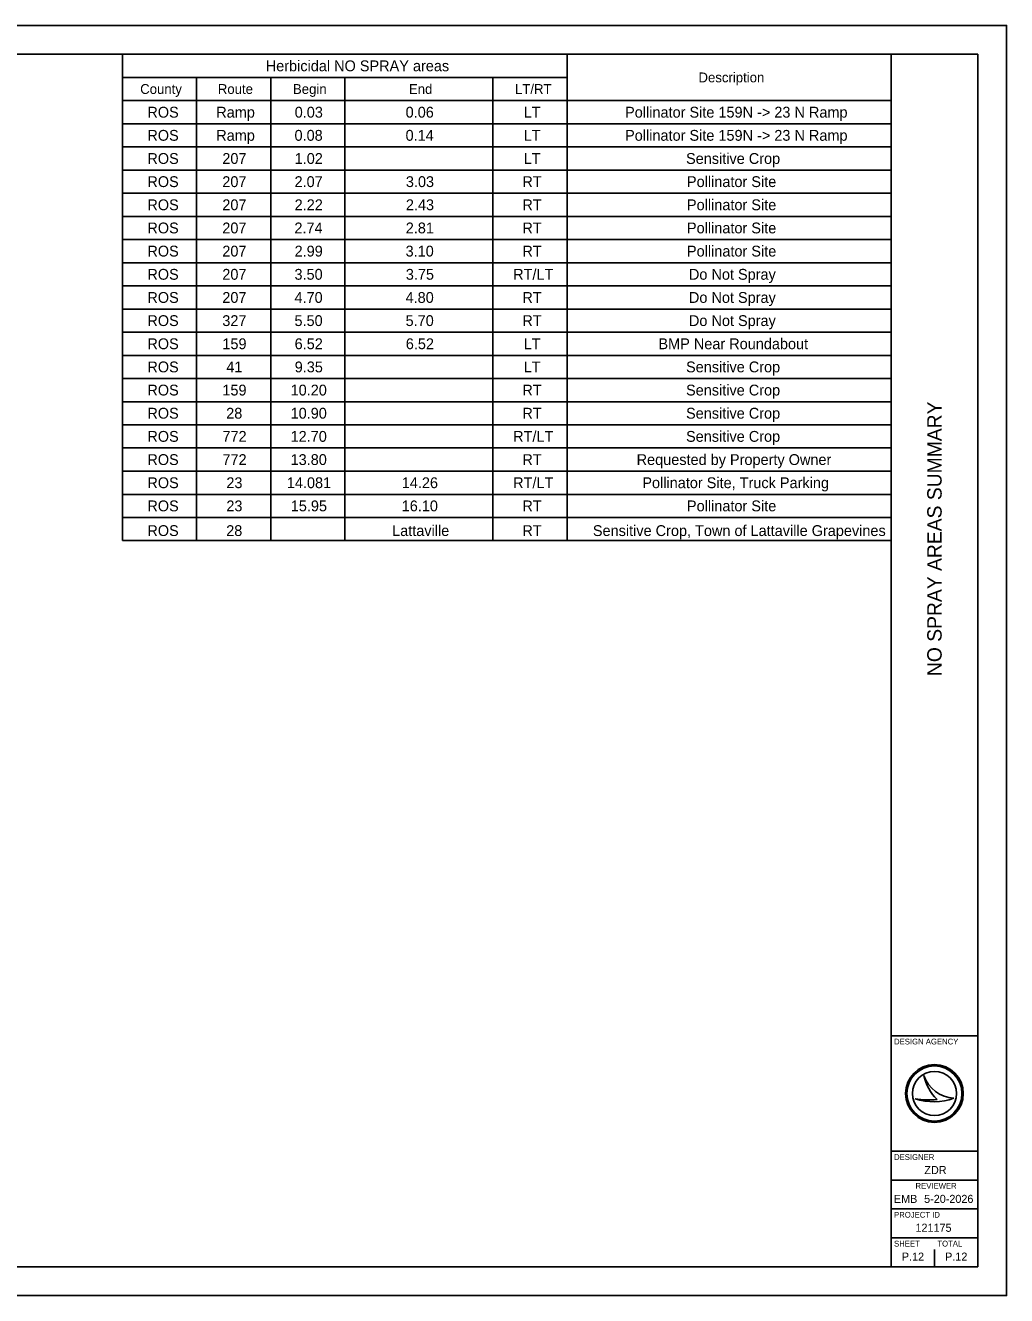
# Model space of a CAD drawing. Extents: x 0 to 34, y 0 to 22.
# Drawn here: x 17 to 34, y 0 to 22 of the extents above; entities that cross this region are included whole.
import ezdxf

# ---------------------------------------------------------------- set-up
doc = ezdxf.new("R2010")
doc.units = 0
for name, color, linetype in [('SH_Border', 7, 'Continuous'), ('SH_Cut_Line', 7, 'Continuous'), ('SH_Data', 7, 'Continuous'), ('SH_Text', 7, 'Continuous')]:
    doc.layers.add(name, color=color, linetype=linetype)

msp = doc.modelspace()

# ---------------------------------------------------------------- linework, layer by layer
at = {"layer": 'SH_Border'}
for p, q in [((32, 0.5), (32, 21.5)), ((32, 4.5), (33.5, 4.5)), ((32, 2.5), (33.5, 2.5)), ((32, 2), (33.5, 2)), ((32, 1.5), (33.5, 1.5)), ((32, 1), (33.5, 1))]:
    msp.add_line(p, q, dxfattribs=at)
msp.add_lwpolyline([(1.5, 21.5), (33.5, 21.5), (33.5, 0.5), (1.5, 0.5)], close=True, dxfattribs=at)
at = {"layer": 'SH_Cut_Line'}
msp.add_lwpolyline([(0, 0), (34, 0), (34, 22), (0, 22)], close=True, dxfattribs=at)
at = {"layer": 'SH_Data'}
for p, q in [((32.567, 3.81), (32.567, 3.81)), ((32.417, 3.41), (32.417, 3.41)), ((32.75, 3.5), (32.75, 3.5)), ((33.087, 3.419), (33.087, 3.419)), ((32.375, 0.675), (32.375, 0.675)), ((32.75, 0.5), (32.75, 0.8))]:
    msp.add_line(p, q, dxfattribs=at)
for radius in [0.5, 0.477, 0.477, 0.382]:
    msp.add_circle((32.75, 3.5), radius, dxfattribs=at)
for centre, radius, start, end in [((33.116, 3.998), 0.58, 198.9257, 198.9319), ((33.347, 3.97), 0.796, 191.6379, 191.6421), ((33.116, 3.998), 0.58, 198.9319, 267.1657), ((33.347, 3.97), 0.796, 191.6421, 226.0947), ((32.739, 4.37), 1.013, 251.4576, 290.0832), ((32.648, 4.654), 1.266, 259.4964, 259.4995), ((32.739, 4.37), 1.013, 251.4527, 251.4576), ((32.648, 4.654), 1.266, 259.4995, 276.6672)]:
    msp.add_arc(centre, radius, start, end, dxfattribs=at)
at = {"layer": 'SH_Text'}
for p, q in [((18.682, 21.5), (32, 21.5)), ((18.682, 21.5), (18.682, 13.076)), ((26.384, 21.5), (26.384, 13.076)), ((32, 21.5), (32, 13.076)), ((18.682, 21.099), (26.384, 21.099)), ((19.966, 21.099), (19.966, 13.076)), ((21.25, 21.099), (21.25, 13.076)), ((22.533, 21.099), (22.533, 13.076)), ((25.1, 21.099), (25.1, 13.076)), ((18.682, 20.698), (32, 20.698)), ((18.682, 20.297), (32, 20.297)), ((18.682, 19.895), (32, 19.895)), ((18.682, 19.494), (32, 19.494)), ((18.682, 19.093), (32, 19.093)), ((18.682, 18.692), (32, 18.692)), ((18.682, 18.291), (32, 18.291)), ((18.682, 17.89), (32, 17.89)), ((18.682, 17.489), (32, 17.489)), ((18.682, 17.088), (32, 17.088)), ((18.682, 16.686), (32, 16.686)), ((18.682, 16.285), (32, 16.285)), ((18.682, 15.884), (32, 15.884)), ((18.682, 15.483), (32, 15.483)), ((18.682, 15.082), (32, 15.082)), ((18.682, 14.681), (32, 14.681)), ((18.682, 14.28), (32, 14.28)), ((18.682, 13.878), (32, 13.878)), ((18.682, 13.477), (32, 13.477)), ((18.682, 13.076), (32, 13.076))]:
    msp.add_line(p, q, dxfattribs=at)

# ---------------------------------------------------------------- texts
at = {"layer": 'SH_Data'}
msp.add_text('NO SPRAY AREAS SUMMARY', height=0.25, rotation=90, dxfattribs=at).set_placement((32.875, 10.73))
for s, height, p in [('DESIGN AGENCY', 0.1, (32.05, 4.35)), ('DESIGNER', 0.1, (32.05, 2.35)), ('ZDR', 0.14, (32.575, 2.105)), ('REVIEWER', 0.1, (32.422, 1.85)), ('EMB', 0.14, (32.047, 1.605)), ('5-20-2026', 0.14, (32.571, 1.605)), ('PROJECT ID', 0.1, (32.05, 1.35)), ('121175', 0.14, (32.421, 1.105)), ('SHEET', 0.1, (32.05, 0.85)), ('TOTAL', 0.1, (32.8, 0.85)), ('P.12', 0.14, (32.185, 0.605)), ('P.12', 0.14, (32.935, 0.605))]:
    msp.add_text(s, height=height, dxfattribs=at).set_placement(p)
at = {"layer": 'SH_Text'}
for s, height, p in [('Herbicidal NO SPRAY areas', 0.18753, (21.164, 21.206)), ('Description', 0.17048, (28.662, 21.014)), ('County', 0.1705, (18.989, 20.813)), ('Route', 0.1705, (20.334, 20.813)), ('Begin', 0.1705, (21.636, 20.813)), ('End', 0.1705, (23.645, 20.813)), ('LT/RT', 0.1705, (25.483, 20.813)), ('ROS', 0.1875, (19.113, 20.403)), ('Ramp', 0.1875, (20.307, 20.403)), ('0.03', 0.1875, (21.666, 20.403)), ('0.06', 0.1875, (23.588, 20.403)), ('LT', 0.1875, (25.633, 20.403)), ('Pollinator Site 159N -> 23 N Ramp', 0.18753, (27.39, 20.403)), ('ROS', 0.1875, (19.113, 20.002)), ('Ramp', 0.1875, (20.307, 20.002)), ('0.08', 0.1875, (21.663, 20.002)), ('0.14', 0.1875, (23.587, 20.002)), ('LT', 0.1875, (25.633, 20.002)), ('Pollinator Site 159N -> 23 N Ramp', 0.18753, (27.39, 20.002)), ('ROS', 0.1875, (19.113, 19.601)), ('207', 0.1875, (20.412, 19.601)), ('1.02', 0.1875, (21.665, 19.601)), ('LT', 0.1875, (25.633, 19.601)), ('Sensitive Crop', 0.18753, (28.446, 19.601)), ('ROS', 0.1875, (19.113, 19.2)), ('207', 0.1875, (20.412, 19.2)), ('2.07', 0.1875, (21.663, 19.2)), ('3.03', 0.1875, (23.592, 19.2)), ('RT', 0.1875, (25.61, 19.2)), ('Pollinator Site', 0.18753, (28.462, 19.2)), ('ROS', 0.1875, (19.113, 18.799)), ('207', 0.1875, (20.412, 18.799)), ('2.22', 0.1875, (21.665, 18.799)), ('2.43', 0.1875, (23.592, 18.799)), ('RT', 0.1875, (25.61, 18.799)), ('Pollinator Site', 0.18753, (28.462, 18.799)), ('ROS', 0.1875, (19.113, 18.398)), ('207', 0.1875, (20.412, 18.398)), ('2.74', 0.1875, (21.661, 18.398)), ('2.81', 0.1875, (23.59, 18.398)), ('RT', 0.1875, (25.61, 18.398)), ('Pollinator Site', 0.18753, (28.462, 18.398)), ('ROS', 0.1875, (19.113, 17.997)), ('207', 0.1875, (20.412, 17.997)), ('2.99', 0.1875, (21.664, 17.997)), ('3.10', 0.1875, (23.587, 17.997)), ('RT', 0.1875, (25.61, 17.997)), ('Pollinator Site', 0.18753, (28.462, 17.997)), ('ROS', 0.1875, (19.113, 17.595)), ('207', 0.1875, (20.412, 17.595)), ('3.50', 0.1875, (21.662, 17.595)), ('3.75', 0.1875, (23.591, 17.595)), ('RT/LT', 0.1875, (25.451, 17.595)), ('Do Not Spray', 0.18753, (28.496, 17.595)), ('ROS', 0.1875, (19.113, 17.194)), ('207', 0.1875, (20.412, 17.194)), ('4.70', 0.1875, (21.662, 17.194)), ('4.80', 0.1875, (23.587, 17.194)), ('RT', 0.1875, (25.61, 17.194)), ('Do Not Spray', 0.18753, (28.496, 17.194)), ('ROS', 0.1875, (19.113, 16.793)), ('327', 0.1875, (20.412, 16.793)), ('5.50', 0.1875, (21.662, 16.793)), ('5.70', 0.1875, (23.587, 16.793)), ('RT', 0.1875, (25.61, 16.793)), ('Do Not Spray', 0.18753, (28.496, 16.793)), ('ROS', 0.1875, (19.113, 16.392)), ('159', 0.1875, (20.413, 16.392)), ('6.52', 0.1875, (21.665, 16.392)), ('6.52', 0.1875, (23.591, 16.392)), ('LT', 0.1875, (25.633, 16.392)), ('BMP Near Roundabout', 0.18753, (27.968, 16.392)), ('ROS', 0.1875, (19.113, 15.991)), ('41', 0.1875, (20.481, 15.991)), ('9.35', 0.1875, (21.666, 15.991)), ('LT', 0.1875, (25.633, 15.991)), ('Sensitive Crop', 0.18753, (28.446, 15.991)), ('ROS', 0.1875, (19.113, 15.59)), ('159', 0.1875, (20.413, 15.59)), ('10.20', 0.1875, (21.595, 15.59)), ('RT', 0.1875, (25.61, 15.59)), ('Sensitive Crop', 0.18753, (28.446, 15.59)), ('ROS', 0.1875, (19.113, 15.189)), ('28', 0.1875, (20.479, 15.189)), ('10.90', 0.1875, (21.595, 15.189)), ('RT', 0.1875, (25.61, 15.189)), ('Sensitive Crop', 0.18753, (28.446, 15.189)), ('ROS', 0.1875, (19.113, 14.788)), ('772', 0.1875, (20.414, 14.788)), ('12.70', 0.1875, (21.595, 14.788)), ('RT/LT', 0.1875, (25.451, 14.788)), ('Sensitive Crop', 0.18753, (28.446, 14.788)), ('ROS', 0.1875, (19.113, 14.386)), ('772', 0.1875, (20.414, 14.386)), ('13.80', 0.1875, (21.595, 14.386)), ('RT', 0.1875, (25.61, 14.386)), ('Requested by Property Owner', 0.18753, (27.59, 14.386)), ('ROS', 0.1875, (19.113, 13.985)), ('23', 0.1875, (20.482, 13.985)), ('14.081', 0.1875, (21.53, 13.985)), ('14.26', 0.1875, (23.521, 13.985)), ('RT/LT', 0.1875, (25.451, 13.985)), ('Pollinator Site, Truck Parking', 0.18753, (27.689, 13.985)), ('ROS', 0.1875, (19.113, 13.584)), ('23', 0.1875, (20.482, 13.584)), ('15.95', 0.1875, (21.598, 13.584)), ('16.10', 0.1875, (23.52, 13.584)), ('RT', 0.1875, (25.61, 13.584)), ('Pollinator Site', 0.18753, (28.462, 13.584)), ('ROS', 0.1875, (19.113, 13.156)), ('28', 0.1875, (20.479, 13.156)), ('Lattaville', 0.1875, (23.354, 13.156)), ('RT', 0.1875, (25.61, 13.156)), ('Sensitive Crop, Town of Lattaville Grapevines', 0.18753, (26.832, 13.156))]:
    msp.add_text(s, height=height, dxfattribs=at).set_placement(p)

doc.saveas('drawing.dxf')
